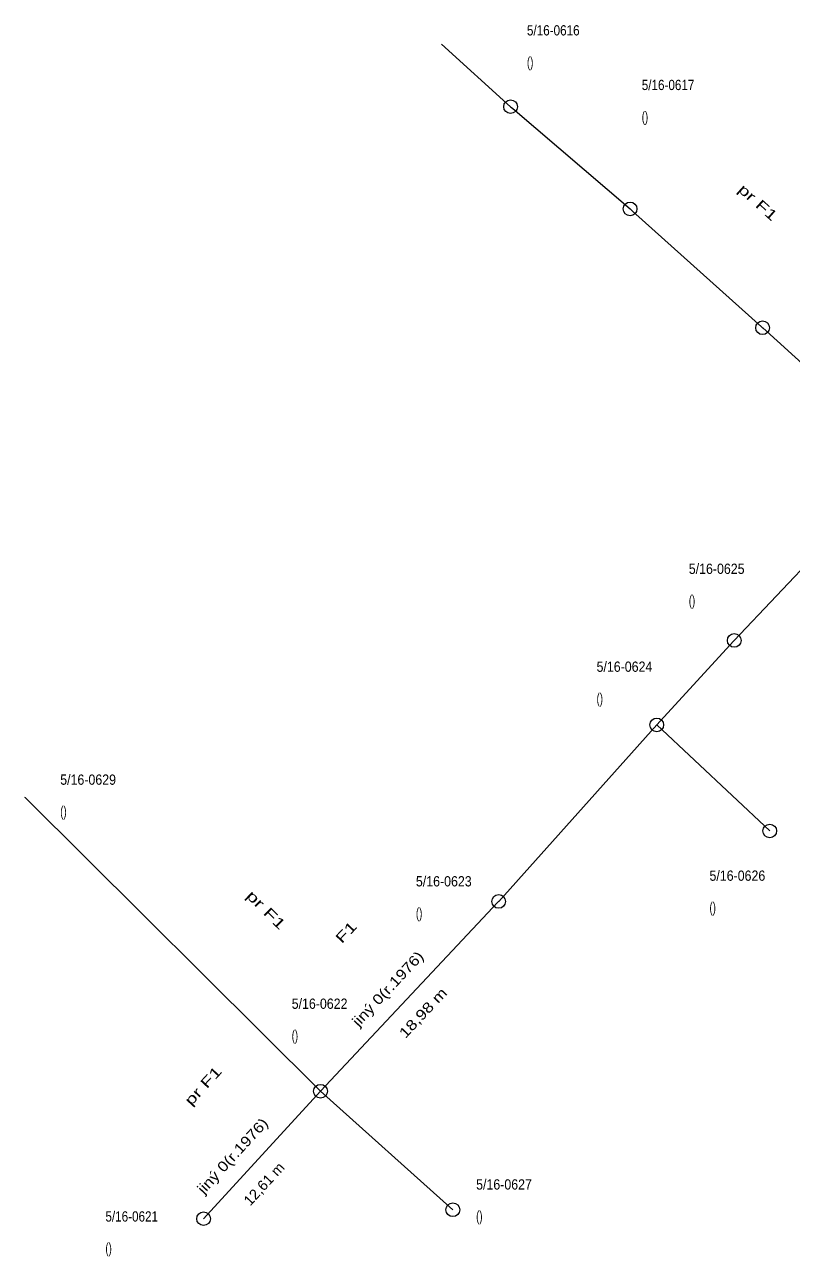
# Model space of a CAD drawing. Extents: x -710854 to -709799, y -1117012 to -1115891.
# Drawn here: x -710574 to -710518.1, y -1116618.6 to -1116528.9 of the extents above; entities that cross this region are included whole.
import ezdxf
from ezdxf.enums import TextEntityAlignment as Align

# ---------------------------------------------------------------- set-up
doc = ezdxf.new("R2010")
doc.units = 0
doc.header["$LTSCALE"] = 0.3
doc.layers.add('38', color=7, linetype='Continuous', lineweight=13)
doc.layers.add('44', color=7, linetype='Continuous', lineweight=13)
doc.layers.add('48', color=7, linetype='Continuous')

msp = doc.modelspace()

# ---------------------------------------------------------------- linework, layer by layer
at = {"layer": '38'}
for p, q in [((-710543.58, -1116530.29), (-710538.535, -1116534.841)), ((-710509.66, -1116560.47), (-710522.227, -1116573.746)), ((-710527.88, -1116579.91), (-710539.408, -1116592.778)), ((-710552.4, -1116606.61), (-710560.93, -1116615.9)), ((-710552.4, -1116606.61), (-710542.75, -1116615.25))]:
    msp.add_line(p, q, dxfattribs=at)
for points in [[(-710538.535, -1116534.841), (-710538.47, -1116534.9), (-710538.371, -1116534.985), (-710529.829, -1116542.298)], [(-710529.829, -1116542.298), (-710529.78, -1116542.34), (-710529.653, -1116542.453), (-710520.24, -1116550.88), (-710520.158, -1116550.954)], [(-710520.158, -1116550.954), (-710520.153, -1116550.959), (-710509.66, -1116560.47)], [(-710522.227, -1116573.746), (-710522.25, -1116573.77), (-710522.281, -1116573.804), (-710527.88, -1116579.91), (-710519.64, -1116587.64)], [(-710573.978, -1116585.183), (-710573.93, -1116585.2), (-710573.81, -1116585.32), (-710552.4, -1116606.61)], [(-710539.408, -1116592.778), (-710539.41, -1116592.78), (-710539.461, -1116592.834), (-710552.4, -1116606.61)]]:
    msp.add_lwpolyline(points, dxfattribs=at)
at = {"layer": '44'}
for centre in [(-710538.535, -1116534.841), (-710529.829, -1116542.298), (-710520.158, -1116550.954), (-710522.227, -1116573.746), (-710527.88, -1116579.91), (-710519.64, -1116587.64), (-710539.408, -1116592.778), (-710552.4, -1116606.61), (-710542.75, -1116615.25), (-710560.93, -1116615.9)]:
    msp.add_circle(centre, 0.5, dxfattribs=at)

# ---------------------------------------------------------------- texts
at = {"layer": '48'}
for s, width, p in [('5/16-0616', 0.85, (-710537.346, -1116529.651)), ('()', 0.7, (-710537.346, -1116531.961)), ('5/16-0617', 0.85, (-710528.974, -1116533.631)), ('()', 0.7, (-710528.974, -1116535.941)), ('5/16-0625', 0.9, (-710525.543, -1116568.901)), ('()', 0.7, (-710525.543, -1116571.211)), ('5/16-0624', 0.9, (-710532.268, -1116576.038)), ('()', 0.7, (-710532.268, -1116578.348)), ('5/16-0629', 0.9, (-710571.381, -1116584.272)), ('()', 0.7, (-710571.381, -1116586.582)), ('5/16-0626', 0.9, (-710524.033, -1116591.271)), ('5/16-0623', 0.9, (-710545.443, -1116591.683)), ('()', 0.7, (-710545.443, -1116593.993)), ('()', 0.7, (-710524.033, -1116593.581)), ('5/16-0622', 0.9, (-710554.501, -1116600.604)), ('()', 0.7, (-710554.501, -1116602.914)), ('5/16-0627', 0.9, (-710541.051, -1116613.779)), ('5/16-0621', 0.85, (-710568.087, -1116616.112)), ('()', 0.7, (-710541.051, -1116616.089)), ('()', 0.7, (-710568.087, -1116618.422))]:
    msp.add_text(s, height=0.75, dxfattribs=dict(at, width=width)).set_placement(p)
for s, rotation, width, p in [('pr F1', 318.17, 1.45, (-710520.7506, -1116542.1015)), ('pr F1', 315.16, 1.5, (-710556.6299, -1116593.6606)), ('F1', 46.79, 1.45, (-710550.2608, -1116595.2758)), ('jiný 0(r.1976)', 46.79, 1.2, (-710547.2182, -1116599.3983)), ('18,98 m', 46.79, 1.25, (-710544.6545, -1116601.1523)), ('pr F1', 47.44, 1.45, (-710560.6882, -1116606.4701)), ('jiný 0(r.1976)', 47.44, 1.2, (-710558.5339, -1116611.5746)), ('12,61 m', 47.44, 1.05, (-710556.243, -1116613.6196))]:
    msp.add_text(s, height=0.75, rotation=rotation, dxfattribs=dict(at, width=width)).set_placement(p, align=Align.CENTER)

doc.saveas('drawing.dxf')
